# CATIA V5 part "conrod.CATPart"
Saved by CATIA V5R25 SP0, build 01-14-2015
Part number: conrod
Bounding box of the stored display mesh (mm): x 0 to 6, y -5 to 60, z -5 to 5
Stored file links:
  C:\Users\Aidata\Downloads\chapter4\chapter4\conrod.CATPart
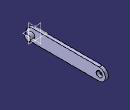
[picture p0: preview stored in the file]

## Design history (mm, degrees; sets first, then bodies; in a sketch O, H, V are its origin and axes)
Body1 (main body)
  Sketch1 on yz-plane, origin (0, 0, 0), H (0, 1, 0), V (0, 0, 1)
    construction line L1 (0, 0) -> (55, 0)
    line L2 (0, 5) -> (55, 5)
    line L3 (55, -5) -> (0, -5)
    arc A1 centre (55, 0) radius 5 from (55, 5) to (55, -5) cw
    arc A2 centre (0, 0) radius 5 from (0, -5) to (0, 5) cw
    circle A3 centre (55, 0) radius 2.5
    distance A2 A1 = 65
    radius A1 = 5
    radius A3 = 2.5
    horizontal: L1 H, L2 H
    tangency: A1 L2, A2 L2, A1 L3, A2 L3
  Pad1: profile Sketch1, direction (1, 0, 0), length 2.5
  Sketch2 on end face of Pad1, origin (2.5, 0, 0), H (0, 1, 0), V (0, 0, 1)
    circle A1 centre (0, 0) radius 2.5
    radius A1 = 2.5
  Pad2: profile Sketch2, direction (1, 0, 0), length 3.5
